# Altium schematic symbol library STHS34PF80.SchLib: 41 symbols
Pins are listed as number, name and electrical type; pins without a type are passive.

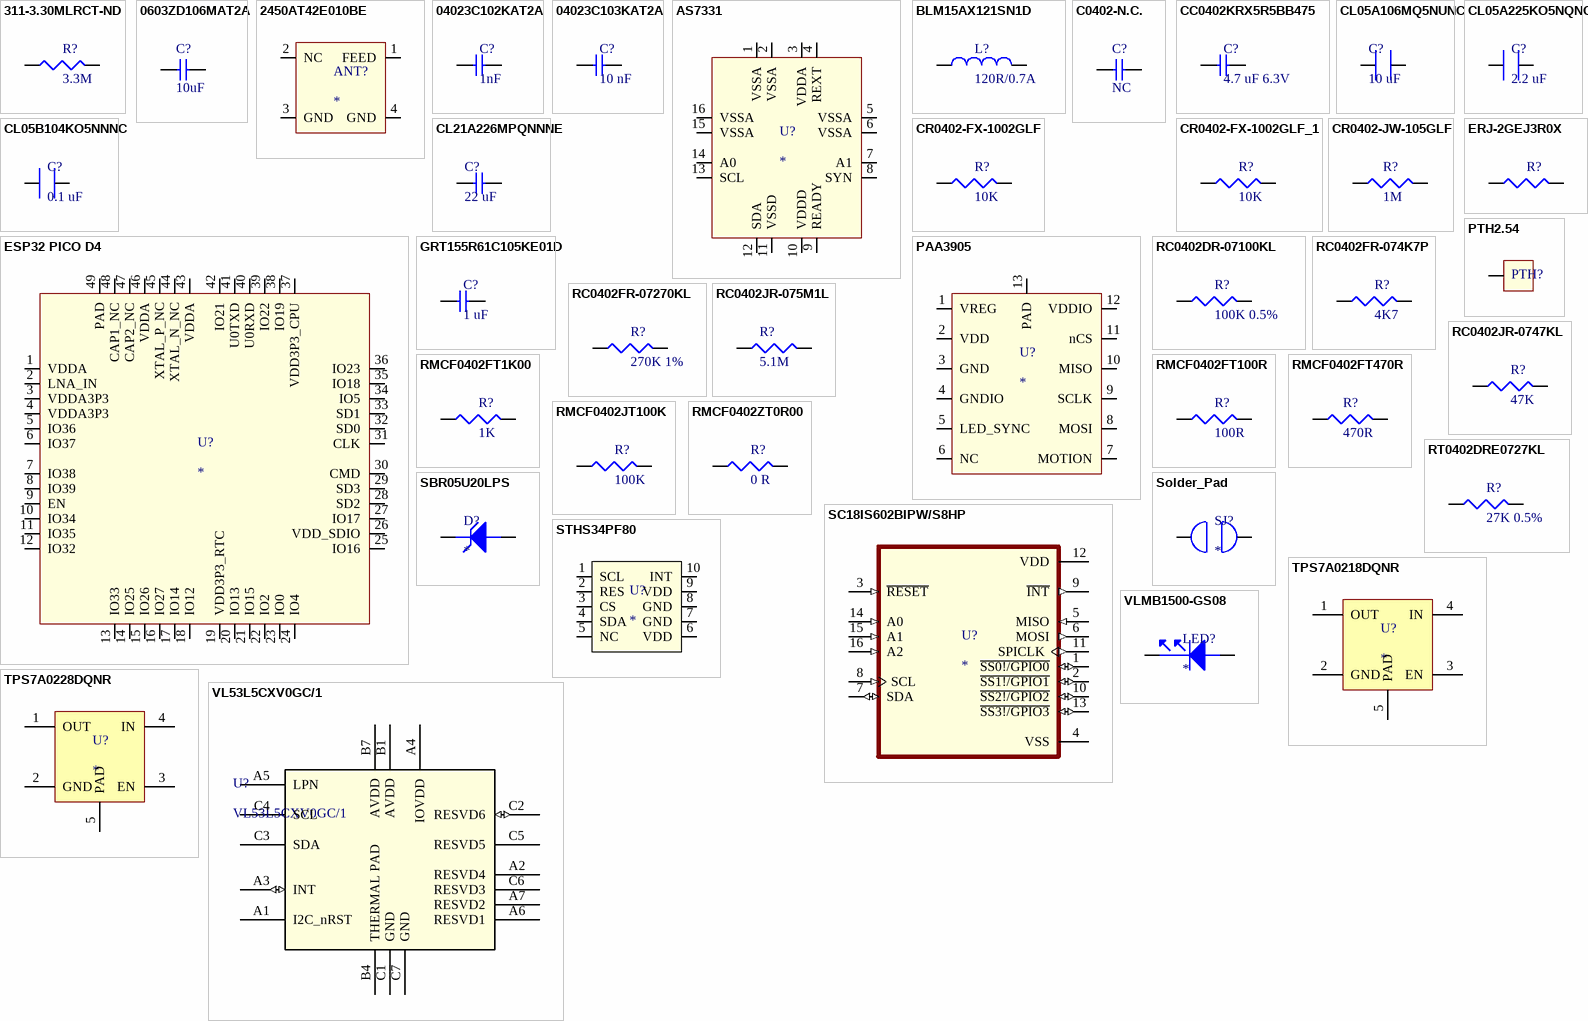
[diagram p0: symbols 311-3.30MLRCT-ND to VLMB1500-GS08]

## 311-3.30MLRCT-ND
designator R?, comment 3.3M
0402 3.3M Fixed Resistor, Metal Glaze/thick Film, 0.0625W, 3300000ohm, 50V, 1% +/-Tol, 100ppm/Cel, Surface Mount, 0402; Manufacturer: Yageo; Manufacturer Part Number: RC0402FR-073M3L; Additional Feature: LASER TRIMMABLE; Power: 62.5mW; Rated Temperature: 70°C; Value: 3.3MR; Temperature Coefficient: 100ppm/°C; Package Height: 0.35mm; Package Length: 1mm; Package Width: 0.5mm
footprint 402RES (0402 package resistor)
pins: 1, 2

## 0603ZD106MAT2A
designator C?, comment 10uF
0603 10 uF Ceramic Capacitor, Multilayer, Ceramic, 10V, 20% +Tol, 20% -Tol, X5R, 15% TC, 10uF, Surface Mount, 0603; Part Number: C0603-10µ-25V-X5R-CL10A106MA8NRNC; Manufacturer: Samsung Electro-Mechanics America; Manufacturer Part Number: CL10A106MA8NRNC; Part number IPS: 00000009948; Part number Norautron: N.A.; Value: 10µF; Note: 25V; Artikkelnr Noca: 20039436; Pad Count: 2; Multilayer: Yes
footprint 0603CAP (0603 capacitor footprint)
pins: 1, 2

## 2450AT42E010BE
designator ANT?
RF/Microwave Antenna, 2400MHz Min, 2480MHz Max; Manufacturer: Johanson; Manufacturer Part Number: 2450AT42E010BE; RF/Microwave Device Type: ANTENNA-OTHER
footprint 2450AT42E010BE (2.4GHz Bluetooth, WLAN, Zigbee™ Chip RF Antenna 2.4GHz ~ 2.48GHz -2dBi Solder Surface Mount)
pins: 1 FEED, 2 NC, 3 GND, 4 GND

## 04023C102KAT2A
designator C?, comment 1nF
0402 1nF Ceramic Capacitor, Multilayer, Ceramic, 25V, 10% +Tol, 10% -Tol, X7R, 15% TC, 0.001uF, Surface Mount, 0402; Manufacturer: Kyocera AVX; Manufacturer Part Number: 04023C102KAT2A; Multilayer: Yes
footprint 402Cap (0402 package capacitor)
pins: 1, 2

## 04023C103KAT2A
designator C?, comment 10 nF
0402 10 nF Ceramic Capacitor, Multilayer, Ceramic, 25V, 10% +Tol, 10% -Tol, X7R, 15% TC, 0.01uF, Surface Mount, 0402; Manufacturer: Kyocera AVX; Manufacturer Part Number: 04023C103KAT2A; Capacitance: 10nF; Multilayer: Yes
footprint 402Cap (0402 package capacitor)
pins: 1, 2

## AS7331
designator U?
AS7331-AQFT OLGA16 Lf Tr; Manufacturer: Osram
footprint AS7331 (Ambient Light Sensors AS7331 3channel UV-A/B/C spectral sensor IC)
pins: 1 VSSA, 2 VSSA, 3 VDDA, 4 REXT, 5 VSSA, 6 VSSA, 7 A1, 8 SYN, 9 READY, 10 VDDD, 11 VSSD, 12 SDA, 13 SCL, 14 A0, 15 VSSA, 16 VSSA

## BLM15AX121SN1D
designator L?, comment 120R/0.7A
0402 Ferrite Chip, 1 Function(s), 0.7A, 2 Pin(s); Manufacturer: Murata; Manufacturer Part Number: BLM15AX121SN1D; DC Resistance-Max: 130mR; Max Frequency: 100MHz; Number of Functions: 1; Output Impedance: 120R; Current Rating: 700mA
footprint 402IND
footprint 402IND
pins: 1, 2

## C0402-N.C.
designator C?, comment NC
Not mounted; Part Number: C0402-N.C.; Manufacturer: N.A.; Assembly: Not mounted; Value: N.C.; Note: Chip Cap; Pad Count: 2
footprint 402Cap (0402 package capacitor)
pins: 1, 2

## CC0402KRX5R5BB475
designator C?, comment 4.7 uF 6.3V
4.7 uF 0402 Ceramic Capacitor, Multilayer, Ceramic, 6.3V, 10% +Tol, 10% -Tol, X5R, 15% TC, 4.7uF, Surface Mount, 0402; Manufacturer: Yageo; Manufacturer Part Number: CC0402KRX5R5BB475; Multilayer: Yes
footprint 402Cap (0402 package capacitor)
pins: 1, 2

## CL05A106MQ5NUNC
designator C?, comment 10 uF
0402 10uF Ceramic Capacitor, Multilayer, Ceramic, 6.3V, 20% +Tol, 20% -Tol, X5R, 15% TC, 10uF, Surface Mount, 0402; Manufacturer: Samsung; Manufacturer Part Number: CL05A106MQ5NUNC; Multilayer: Yes
footprint 402Cap (0402 package capacitor)
pins: 1, 2

## CL05A225KO5NQNC
designator C?, comment 2.2 uF
0402 2.2 uF Ceramic Capacitor, Multilayer, Ceramic, 16V, 10% +Tol, 10% -Tol, X5R, 15% TC, 2.2uF, Surface Mount, 0402; Manufacturer: Samsung; Manufacturer Part Number: CL05A225KO5NQNC; Multilayer: Yes
footprint 402Cap (0402 package capacitor)
pins: 1, 2

## CL05B104KO5NNNC
designator C?, comment 0.1 uF
0402 0.1 uF Ceramic Capacitor, Multilayer, Ceramic, 16V, 10% +Tol, 10% -Tol, X7R, 15% TC, 0.1uF, Surface Mount, 0402; Manufacturer: Samsung; Manufacturer Part Number: CL05B104KO5NNNC; Capacitance: 100nF; Multilayer: Yes
footprint 402Cap (0402 package capacitor)
pins: 1, 2

## CL21A226MPQNNNE
designator C?, comment 22 uF
0402 22 uF Ceramic Capacitor, Multilayer, Ceramic, 10V, 20% +Tol, 20% -Tol, X5R, 15% TC, 22uF, Surface Mount, 0805; Manufacturer: Kyocera AVX; Manufacturer Part Number: 0402YC224KAT2A; Capacitance: 220nF; Multilayer: Yes; Negative Tolerance: 10%; Rated DC Voltage (URdc): 16V; Temperature Characteristics Code: X7R
footprint 402Cap (0402 package capacitor)
pins: 1, 2

## CR0402-FX-1002GLF
designator R?, comment 10K
0402 10K Fixed Resistor, Metal Glaze/thick Film, 0.0625W, 10000ohm, 50V, 1% +/-Tol, 100ppm/Cel, Surface Mount, 0402; Manufacturer: Bourns; Manufacturer Part Number: CR0402-FX-1002GLF; Rated Power Dissipation (P): 62.5mW; Rated Temperature: 70°C; Resistance: 10kR; Temperature Coefficient: 100ppm/°C; Package Height: 0.35mm; Package Length: 1mm; Package Width: 0.5mm
footprint 402RES (0402 package resistor)
pins: 1, 2

## CR0402-FX-1002GLF_1
designator R?, comment 10K
0402 10K Fixed Resistor, Metal Glaze/thick Film, 0.0625W, 10000ohm, 50V, 1% +/-Tol, 100ppm/Cel, Surface Mount, 0402; Manufacturer: Bourns; Manufacturer Part Number: CR0402-FX-1002GLF; Rated Power Dissipation (P): 62.5mW; Rated Temperature: 70°C; Resistance: 10kR; Temperature Coefficient: 100ppm/°C; Package Height: 0.35mm; Package Length: 1mm; Package Width: 0.5mm
footprint 402RES (0402 package resistor)
pins: 1, 2

## CR0402-JW-105GLF
designator R?, comment 1M
0402 1M Res Thick Film 0402 1M Ohm 5% 1/16W ±200ppm/°C Molded SMD SMD Paper Tape on Plastic Reel; Manufacturer: Bourns; Manufacturer Part Number: CR0402-JW-105GLF; Rated Power Dissipation (P): 62.5mW; Rated Temperature: 70°C; Resistance: 1MR; Working Voltage: 50V; Package Height: 0.35mm; Package Length: 1mm; Package Width: 0.5mm
footprint 402RES (0402 package resistor)
pins: 1, 2

## ERJ-2GEJ3R0X
designator R?, comment 3R  (value not drawn)
3R 0402 Fixed Resistor, Metal Glaze/thick Film, 0.1W, 3ohm, 50V, 5% +/-Tol, -100,600ppm/Cel, Surface Mount, 0402; Manufacturer: Panasonic; Manufacturer Part Number: ERJ-2GEJ3R0X; Rated Power Dissipation (P): 100mW; Rated Temperature: 70°C; Temperature Coefficient: 600ppm/°C; Package Height: 0.35mm; Package Length: 1mm; Package Width: 0.5mm; Reference Standard: AEC-Q200
footprint 402RES (0402 package resistor)
pins: 1, 2

## ESP32 PICO D4
designator U?
Bluetooth, WiFi 802.11b/g/n, Bluetooth v4.2 +EDR, Class 1, 2 and 3 Transceiver Module 2.4GHz ~ 2.5GHz Surface Mount; Manufacturer: Espressif Systems; Manufacturer Part Number: ESP32-PICO-D4
footprint ESP32 PICO D4 (Bluetooth, WiFi 802.11b/g/n, Bluetooth v4.2 +EDR, Class 1, 2 and 3 Transceiver Module 2.4GHz ~ 2.5GHz Surface Mount)
pins: 1 VDDA, 2 LNA_IN, 3 VDDA3P3, 4 VDDA3P3, 5 IO36, 6 IO37, 7 IO38, 8 IO39, 9 EN, 10 IO34, 11 IO35, 12 IO32, 13 IO33, 14 IO25, 15 IO26, 16 IO27, 17 IO14, 18 IO12, 19 VDD3P3_RTC, 20 IO13, 21 IO15, 22 IO2, 23 IO0, 24 IO4, 25 IO16, 26 VDD_SDIO, 27 IO17, 28 SD2, 29 SD3, 30 CMD, 31 CLK, 32 SD0, 33 SD1, 34 IO5, 35 IO18, 36 IO23, 37 VDD3P3_CPU, 38 IO19, 39 IO22, 40 U0RXD, 41 U0TXD, 42 IO21, 43 VDDA, 44 XTAL_N_NC, 45 XTAL_P_NC, 46 VDDA, 47 CAP2_NC, 48 CAP1_NC, 49 PAD

## GRT155R61C105KE01D
designator C?, comment 1 uF
0402 1 uF Ceramic Capacitor, Multilayer, Ceramic, 16V, 10% +Tol, 10% -Tol, X5R, 15% TC, 1uF, Surface Mount, 0402; Manufacturer: Murata; Manufacturer Part Number: GRT155R61C105KE01D; Multilayer: Yes; Reference Standard: AEC-Q200
footprint 402Cap (0402 package capacitor)
pins: 1, 2

## PAA3905
designator U?
PAA3905E1-Q PixArt Imaging's optical motion tracking chip specifically designed for low light condition / operation
footprint PAA3905E1-Q (PixArt Imaging's optical motion  tracking chip s)
pins: 1 VREG, 2 VDD, 3 GND, 4 GNDIO, 5 LED_SYNC, 6 NC, 7 MOTION, 8 MOSI, 9 SCLK, 10 MISO, 11 nCS, 12 VDDIO, 13 PAD

## PTH2.54
designator PTH?  (value not drawn)
Standard 0.1" plated through hole for pin headers
footprint PTH2.54 (Standard 0.1" plated through hole)
pins: 1

## RC0402DR-07100KL
designator R?, comment 100K 0.5%
0402 100K Fixed Resistor, Metal Glaze/thick Film, 0.0625W, 100000ohm, 50V, 0.5% +/-Tol, 100ppm/Cel, Surface Mount, 0402; Manufacturer: Yageo; Manufacturer Part Number: RC0402DR-07100KL; Additional Feature: LASER TRIMMABLE; Rated Power Dissipation (P): 62.5mW; Rated Temperature: 70°C; Resistance: 100kR; Temperature Coefficient: 100ppm/°C; Package Height: 0.35mm; Package Length: 1mm; Package Width: 0.5mm
footprint 402RES (0402 package resistor)
pins: 1, 2

## RC0402FR-074K7P
designator R?, comment 4K7
0402 4K7 Fixed Resistor, Metal Glaze/thick Film, 0.0625W, 4700ohm, 50V, 1% +/-Tol, 150ppm/Cel, Surface Mount, 0402; Manufacturer: Yageo; Manufacturer Part Number: RC0402FR-074K7P; Additional Feature: LASER TRIMMABLE; Rated Power Dissipation (P): 62.5mW; Rated Temperature: 70°C; Resistance: 4.7kR; Temperature Coefficient: 150ppm/°C
footprint 402RES (0402 package resistor)
pins: 1, 2

## RC0402FR-07270KL
designator R?, comment 270K 1%
0402 270K 1% Fixed Resistor, Metal Glaze/thick Film, 0.0625W, 270000ohm, 50V, 1% +/-Tol, 100ppm/Cel, Surface Mount, 0402; Manufacturer: Yageo; Manufacturer Part Number: RC0402FR-07270KL; Additional Feature: LASER TRIMMABLE; Rated Power Dissipation (P): 62.5mW; Rated Temperature: 70°C; Resistance: 270kR; Temperature Coefficient: 100ppm/°C; Package Height: 0.35mm; Package Length: 1mm; Package Width: 0.5mm
footprint 402RES (0402 package resistor)
pins: 1, 2

## RC0402JR-075M1L
designator R?, comment 5.1M
0402 5.1M Fixed Resistor, Metal Glaze/thick Film, 0.0625W, 5100000ohm, 50V, 5% +/-Tol, 100ppm/Cel, Surface Mount, 0402; Manufacturer: Yageo; Manufacturer Part Number: RC0402JR-075M1L; Additional Feature: LASER TRIMMABLE; Rated Power Dissipation (P): 62.5mW; Rated Temperature: 70°C; Resistance: 5.1MR; Temperature Coefficient: 100ppm/°C; Package Height: 0.35mm; Package Length: 1mm; Package Width: 0.5mm
footprint 402RES (0402 package resistor)
pins: 1, 2

## RC0402JR-0747KL
designator R?, comment 47K
0402 47K Fixed Resistor, Metal Glaze/thick Film, 0.0625W, 47000ohm, 50V, 5% +/-Tol, 100ppm/Cel, Surface Mount, 0402; Manufacturer: Yageo; Manufacturer Part Number: RC0402JR-0747KL; Additional Feature: LASER TRIMMABLE; Rated Power Dissipation (P): 62.5mW; Rated Temperature: 70°C; Resistance: 47kR; Temperature Coefficient: 100ppm/°C; Package Height: 0.35mm; Package Length: 1mm; Package Width: 0.5mm
footprint 402RES (0402 package resistor)
pins: 1, 2

## RMCF0402FT1K00
designator R?, comment 1K
0402 1K Fixed Resistor, Metal Glaze/thick Film, 0.063W, 1000ohm, 50V, 1% +/-Tol, 100ppm/Cel, Surface Mount, 0402; Manufacturer: Stackpole Electronics; Manufacturer Part Number: RMCF0402FT1K00; Rated Power Dissipation (P): 63mW; Rated Temperature: 70°C; Resistance: 1kR; Temperature Coefficient: 100ppm/°C; Package Height: 0.3mm; Package Length: 1mm; Package Width: 0.5mm; Reference Standard: AEC-Q200
footprint 402RES (0402 package resistor)
pins: 1, 2

## RMCF0402FT100R
designator R?, comment 100R
0402 100R Fixed Resistor, Metal Glaze/thick Film, 0.063W, 100ohm, 50V, 1% +/-Tol, 100ppm/Cel, Surface Mount, 0402; Manufacturer: Stackpole Electronics; Manufacturer Part Number: RMCF0402FT100R; Rated Power Dissipation (P): 63mW; Rated Temperature: 70°C; Temperature Coefficient: 100ppm/°C; Package Height: 0.3mm; Package Length: 1mm; Package Width: 0.5mm; Reference Standard: AEC-Q200
footprint 402RES (0402 package resistor)
pins: 1, 2

## RMCF0402FT470R
designator R?, comment 470R
0402 470R Fixed Resistor, Metal Glaze/thick Film, 0.063W, 470ohm, 50V, 1% +/-Tol, 100ppm/Cel, Surface Mount, 0402; Manufacturer: Stackpole Electronics; Manufacturer Part Number: RMCF0402FT470R; Rated Power Dissipation (P): 63mW; Rated Temperature: 70°C; Temperature Coefficient: 100ppm/°C; Package Height: 0.3mm; Package Length: 1mm; Package Width: 0.5mm; Reference Standard: AEC-Q200
footprint 402RES (0402 package resistor)
pins: 1, 2

## RMCF0402JT100K
designator R?, comment 100K
0402 100K Fixed Resistor, 5% Metal Glaze/thick Film, 0.063W, 100000ohm, 50V, 5% +/-Tol, 100ppm/Cel, Surface Mount, 0402; Manufacturer: Stackpole Electronics; Manufacturer Part Number: RMCF0402JT100K; Rated Power Dissipation (P): 63mW; Rated Temperature: 70°C; Resistance: 100kR; Temperature Coefficient: 100ppm/°C; Package Height: 0.3mm; Package Length: 1mm; Package Width: 0.5mm; Reference Standard: AEC-Q200
footprint 402RES (0402 package resistor)
pins: 1, 2

## RMCF0402ZT0R00
designator R?, comment 0 R
0402 0R Fixed Resistor, Metal Glaze/thick Film, 0.063W, 0ohm, Surface Mount, 0402; Manufacturer: Stackpole Electronics; Manufacturer Part Number: RMCF0402ZT0R00; Rated Power Dissipation (P): 63mW; Rated Temperature: 70°C; Working Voltage: 50V; Package Height: 0.3mm; Package Length: 1mm; Package Width: 0.5mm; Reference Standard: AEC-Q200
footprint 402RES (0402 package resistor)
pins: 1, 2

## RT0402DRE0727KL
designator R?, comment 27K 0.5%
0402 27K Fixed Resistor, Thin Film, 0.0625W, 27000ohm, 50V, 0.5% +/-Tol, 50ppm/Cel, Surface Mount, 0402; Manufacturer: Yageo; Manufacturer Part Number: RT0402DRE0727KL; Additional Feature: HIGH PRECISION; Rated Power Dissipation (P): 62.5mW; Rated Temperature: 70°C; Resistance: 27kR; Temperature Coefficient: 50ppm/°C; Package Height: 0.3mm; Package Length: 1mm; Package Width: 0.5mm
footprint 402RES (0402 package resistor)
pins: 1, 2

## SBR05U20LPS
designator D?
Rectifier Diode, 1 Phase, 1 Element, 0.5A, 20V V(RRM), Silicon; Manufacturer: Diodes; Manufacturer Part Number: SBR05U20LPS-7; Package Body Material: Plastic; Forward Voltage-Max (VF): 280mV; Non-rep Pk Forward Current-Max: 6A; Number of Elements: 1; Max Output Current: 500mA; Time @ Peak Reflow Temperature-Max (s): 40s; Qualification Status: Not Qualified
footprint SBR05U20LPS-7 (Diode Super Barrier 20 V 500mA Surface Mount DFN1006H4-2)
pins: 1, 2

## SC18IS602BIPW/S8HP
designator U?
I2C Bus Controller, CMOS, PDSO16; Manufacturer: NXP Semiconductors; MF: NXP USA; MP: SC18IS602BIPW/S8HP; Package Body Material: Plastic; Max Supply Voltage: 3.6V; Min Supply Voltage: 2.4V; Supply Voltage-Nom: 3V; Time @ Peak Reflow Temperature-Max (s): 30s
footprint SOP65P640X110-16N
pins: 1 ~{SS0!/GPIO0} (io), 2 ~{SS1!/GPIO1} (io), 3 ~{RESET} (in), 4 VSS (power), 5 MISO (in), 6 MOSI (out), 7 SDA (io), 8 SCL (in), 9 ~{INT} (out), 10 ~{SS2!/GPIO2} (io), 11 SPICLK (out), 12 VDD (power), 13 ~{SS3!/GPIO3} (io), 14 A0 (in), 15 A1 (in), 16 A2 (in)

## Solder_Pad
designator SJ?
footprint SolderPadOpen
pins: 1, 2

## STHS34PF80
designator U?
Infrared Detectors Low-power, high-sensitivity infrared sensor for presence and motion detection; Manufacturer: STMicroelectronics; Manufacturer Part Number: STHS34PF80TR
footprint STHS34PF80TR (OLGA-10L 3.2 x 4.2 x 1.455 mm package)
pins: 1 SCL, 2 RES, 3 CS, 4 SDA, 5 NC, 6 VDD, 7 GND, 8 GND, 9 VDD, 10 INT

## TPS7A0218DQNR
designator U?
1V8 Fixed Positive LDO Regulator, 1.8V, 0.45V Dropout, PDSO4; Manufacturer: Texas Instruments; Manufacturer Part Number: TPS7A0218PDQNR
footprint TPS7A02 (TPS7A02 LDO)
pins: 1 OUT, 2 GND, 3 EN, 4 IN, 5 PAD

## TPS7A0228DQNR
designator U?
Fixed Positive LDO Regulator, 2.8V, 0.36V Dropout, PDSO4; Manufacturer: Texas Instruments; Manufacturer Part Number: TPS7A0228PDQNR
footprint TPS7A02 (TPS7A02 LDO)
pins: 1 OUT, 2 GND, 3 EN, 4 IN, 5 PAD

## VL53L5CXV0GC/1
designator U?
VL53L5CX Series 400 cm Time-of-Flight Multizone Ranging Sensor - OLGA-16; Mfr_Name: STMicroelectronics
footprint LGA_CXV0GC/1_STM
pins: A1 I2C_nRST, A2 RESVD4, A3 INT (io), A4 IOVDD (power), A5 LPN, A6 RESVD1, A7 RESVD2, B1 AVDD (power), B4 THERMAL PAD, B7 AVDD (power), C1 GND, C2 RESVD6 (io), C3 SDA, C4 SCL, C5 RESVD5, C6 RESVD3, C7 GND

## VLMB1500-GS08
designator LED?
Single Color LED, Blue, 0.5mm; Manufacturer: Vishay; Manufacturer Part Number: VLMB1500-GS08; Shape: Rectangular; Forward Current-Max: 30mA; Forward Voltage-Max: 3.15V; Luminous Intensity-Nom: 28.1mcd; Number of Functions: 1; Viewing Angle: 130°; Overall Height: 0.35mm
footprint 0402LED (0402 package size footprint for leds)
pins: 1, 2

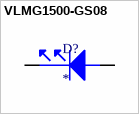
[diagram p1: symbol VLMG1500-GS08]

## VLMG1500-GS08
designator D?
Single Color LED, Yellow Green, 0.5mm; Manufacturer: Vishay; Manufacturer Part Number: VLMG1500-GS08; Color: Green,Yellow; Shape: Rectangular; Forward Current-Max: 30mA; Forward Voltage-Max: 2.4V; Luminous Intensity-Nom: 90mcd; Number of Functions: 1; Reverse Voltage-Max: 5V; Viewing Angle: 130°; Overall Height: 0.35mm
footprint 0402LED (0402 package size footprint for leds)
pins: 1, 2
